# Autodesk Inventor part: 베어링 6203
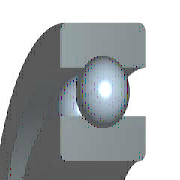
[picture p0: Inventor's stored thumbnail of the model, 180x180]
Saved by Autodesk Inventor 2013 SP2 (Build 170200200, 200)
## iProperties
IsCustomPart: 0
Created: 2016-04
Part Number: 베어링 6203
Material: 강철, 연강
Description: 깊은 그루브 볼 베어링
Document SubType Name: Modeling
Standard: KS B 2023
Designer: mdu
Standards Organization: KS
Language: ko-KR
Size Designation: 6203 - 17 x 40 x 12
Categories: <MemberInstance><Categories><Category DisplayName="샤프트 부품" InternalName="7f7aeb1f-a693-4053-b835-cee3144e0d98" Mnemonic="SHFT"><Category DisplayName="베어링" Inter
Density: 7.86 g/cm^3
Mass: 64.9809 g
Surface Area: 64.3582 cm^2
Volume: 8.26729 cm^3
Author: mdu
Revision Number: 1
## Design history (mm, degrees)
sketch "스케치" dims "d0" = 5.98 (= -0.26 x WD + 0.26 x BD)
  geometry: L1 (3.01, 14.25)-(8.99, 14.25); L2 (6, 14.25)-(6, 11.26); L3 (6, 14.25)-(6, 17.24); L4 (3.778, 12.249)-(0, 12.249); L5 (0, 8.5)-(12, 8.5); L6 (3.778, 16.251)-(0, 16.251); L7 (0, 20)-(12, 20); L8 (12, 8.5)-(12, 12.249); L9 (8.222, 12.249)-(12, 12.249); L10 (8.222, 16.251)-(12, 16.251); L11 (12, 20)-(12, 16.251); L12 (-1.4, 0)-(8.4, 0) reference; L13 (0, -0.3)-(0, 5.3) reference
  constraints: 22 end point, 4 point on line, 2 collinear, 2 perpendicular, 2 symmetric about line, 1 midpoint, 1 parallel, 14 other
  dimensions: "d9" = 17 diameter of L5 L12 (= WD); "d11" = 40 diameter of L7 L12 (= BD); "d12" = 12 distance between parallel lines of L8 L13 (= KB); "d13" = 24.498 diameter of L9 L12 (= 0.326 x BD + 0.674 x WD)
revolve "본체" stored, may be unused: angle "d6" = 90 deg
revolve "볼" stored, may be unused: angle "d7" = 90 deg
pattern_circular "IDS_ARRAYBALL[SIMPL:T]" dims angle "d3" = 360 deg
body "Solid1"
fillet "모깎기1" dims "d1" = 0.6 (= KRS)
other parameters: "WD" = 17 [user parameter; used in 5 equation terms], "BD" = 40 [user parameter; used in 5 equation terms], "KB" = 12 [user parameter; used in 1 equation term], "KRS" = 0.6 [user parameter; used in 1 equation term], "d4" = 0, "d5" = 0, "d8" = 0, "d14" = 0, "d15" = 0, "BBA" = 0 [user parameter], "BC0" = 4750000 [user parameter], "BC" = 9560000 [user parameter], "WR" = 8.5 (= 0.5 x WD) [user parameter]
